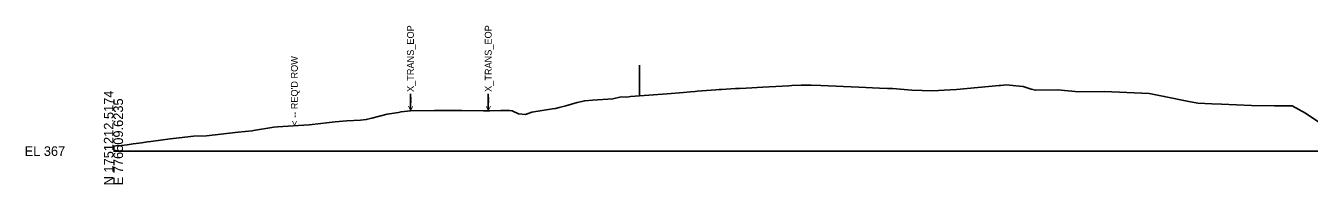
# Model space of a CAD drawing. Extents: x 776426 to 854588, y 1736205 to 1756790.
# Drawn here: x 805845.1 to 806220.7, y 1739205.1 to 1739251.4 of the extents above; entities that cross this region are included whole.
import ezdxf

# ---------------------------------------------------------------- set-up
doc = ezdxf.new("R2010")
doc.units = 0
for name, color, linetype in [('DTM CONTOURS_MAJOR_TX', 7, 'Continuous'), ('DTM_X_FLOW_ARROWS', 7, 'Continuous'), ('TRANS_UNPAVED_SHOULDERS', 7, 'Continuous'), ('X_TRANS_EOP', 7, 'Continuous'), ('XS_P_ROW', 7, 'Continuous'), ('XS_X_PAVEMENT', 7, 'Continuous')]:
    doc.layers.add(name, color=color, linetype=linetype)

msp = doc.modelspace()

# ---------------------------------------------------------------- linework, layer by layer
at = {"layer": 'DTM CONTOURS_MAJOR_TX'}
msp.add_line((805870.79, 1739214.76), (806370.79, 1739214.76), dxfattribs=at)
at = {"layer": 'DTM_X_FLOW_ARROWS'}
msp.add_lwpolyline([(805870.79, 1739216.23), (805871.48, 1739216.28), (805873.13, 1739216.43), (805874.77, 1739216.61), (805876.53, 1739216.85), (805877.47, 1739217), (805878.98, 1739217.21), (805880.79, 1739217.48), (805881.73, 1739217.56), (805887.35, 1739218.34), (805889.98, 1739218.68), (805894.2, 1739219.12), (805897.98, 1739219.25), (805907.29, 1739220.31), (805911.37, 1739220.7), (805911.76, 1739220.77), (805917.69, 1739221.74), (805918.83, 1739221.81), (805928.03, 1739222.46), (805931.43, 1739222.86), (805933.17, 1739223.03), (805935.69, 1739223.27), (805939.1, 1739223.6), (805943.07, 1739223.84), (805944.73, 1739223.95), (805946.37, 1739224.43), (805950.83, 1739225.6), (805954.17, 1739226.05), (805954.94, 1739226.24), (805957.71, 1739226.48), (805964.68, 1739226.59), (805968.96, 1739226.64), (805972.77, 1739226.6), (805979.1, 1739226.49), (805980.44, 1739226.49), (805980.91, 1739226.49), (805984.16, 1739226.58), (805986.7, 1739226.58), (805987.44, 1739226.57), (805989.33, 1739225.68), (805991.31, 1739225.44), (805993.18, 1739226.18), (805999.28, 1739227.08), (806000.17, 1739227.21), (806001.19, 1739227.51), (806003.15, 1739228.01), (806006.48, 1739228.97), (806008.69, 1739229.47), (806010.97, 1739229.63), (806016.91, 1739230.07), (806019.38, 1739230.61), (806020.96, 1739230.56), (806022.03, 1739230.67), (806032.78, 1739231.48), (806037.62, 1739231.9), (806039.68, 1739232.06), (806041.01, 1739232.22), (806041.6, 1739232.27), (806047, 1739232.65), (806048.03, 1739232.72), (806048.75, 1739232.77), (806052.84, 1739233.03), (806053.94, 1739233.08), (806055.95, 1739233.19), (806060.82, 1739233.46), (806066.47, 1739233.73), (806068.37, 1739233.83), (806069.32, 1739233.88), (806072, 1739233.99), (806073.32, 1739234.04), (806074.9, 1739233.99), (806077.79, 1739233.97), (806088.87, 1739233.42), (806094.95, 1739233.19), (806097.23, 1739233.05), (806098.7, 1739233.01), (806104.44, 1739232.53), (806110.44, 1739232.4), (806115.57, 1739232.62), (806117.5, 1739232.72), (806129.91, 1739233.93), (806130.35, 1739233.96), (806131.19, 1739234.03), (806132.08, 1739234.09), (806134.85, 1739233.82), (806136.93, 1739233.61), (806139.35, 1739232.9), (806140.65, 1739232.56), (806146.99, 1739232.69), (806153.22, 1739232.1), (806160.79, 1739232.22), (806173.8, 1739231.55), (806178.26, 1739230.72), (806185.46, 1739229.23), (806188.11, 1739228.79), (806192.16, 1739228.55), (806195, 1739228.46), (806203.82, 1739228.07), (806210.49, 1739228), (806215.7, 1739227.98), (806219.55, 1739225.83), (806224.03, 1739222.84)], dxfattribs=at)
at = {"layer": 'TRANS_UNPAVED_SHOULDERS'}
msp.add_line((806024.74, 1739239.87), (806024.74, 1739230.87), dxfattribs=at)
msp.add_line((806024.74, 1739239.87), (806024.74, 1739230.87), dxfattribs=at)
at = {"layer": 'X_TRANS_EOP'}
for p, q in [((805957.7, 1739231.48), (805957.7, 1739226.48)), ((805957.7, 1739231.48), (805957.7, 1739226.48)), ((805980.44, 1739231.49), (805980.44, 1739226.49)), ((805980.44, 1739231.49), (805980.44, 1739226.49))]:
    msp.add_line(p, q, dxfattribs=at)

# ---------------------------------------------------------------- texts
at = {"layer": 'DTM CONTOURS_MAJOR_TX'}
for s, p in [('N 1751212.5174', (805870.79, 1739204.76)), ('E 776509.6235', (805873.59, 1739204.76))]:
    msp.add_text(s, height=2.8, rotation=90, dxfattribs=at).set_placement(p)
msp.add_text('EL 367', height=2.8, dxfattribs=at).set_placement((805844.79, 1739213.36))
at = {"layer": 'XS_P_ROW'}
msp.add_text("< -- REQ'D ROW", height=2, rotation=90, dxfattribs=at).set_placement((805924.73, 1739222.16))
at = {"layer": 'XS_X_PAVEMENT'}
for p in [(805958.7, 1739226.48), (805981.44, 1739226.49)]:
    msp.add_text('< --  X_TRANS_EOP', height=2, rotation=90, dxfattribs=at).set_placement(p)

doc.saveas('drawing.dxf')
